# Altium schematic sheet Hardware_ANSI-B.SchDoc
size 431 x 279 mm; Date: Not shown in title block; ApprovedBy: Not shown in title block; CheckedBy: Not shown in title block; Author: Not shown in title block; CompanyName: Not shown in title block; Engineer: Not shown in title block; Organization: Not shown in title block; Address1: Not shown in title block; Address2: Not shown in title block; Address3: Not shown in title block; Address4: Not shown in title block; DocumentNumber: 1; Revision: Use project parameter SCH_Rev; SheetNumber: 1; SheetTotal: 1; PageSetup: Record=PageOptions|CenterHorizontal=True|CenterVertical=True|PrintScale=1.00|XCorrection=1.00|YCorrection=1.00|PrintKind=0|BorderSize=5000000|LeftOffset=0|BottomOffset=0|Orientation=2|PaperLength=1000|PaperWidth=1000|Scale=100|PaperSource=15|PrintQuality=600|MediaType=1|DitherType=10|PaperKind=Letter|PrintScaleMode=1
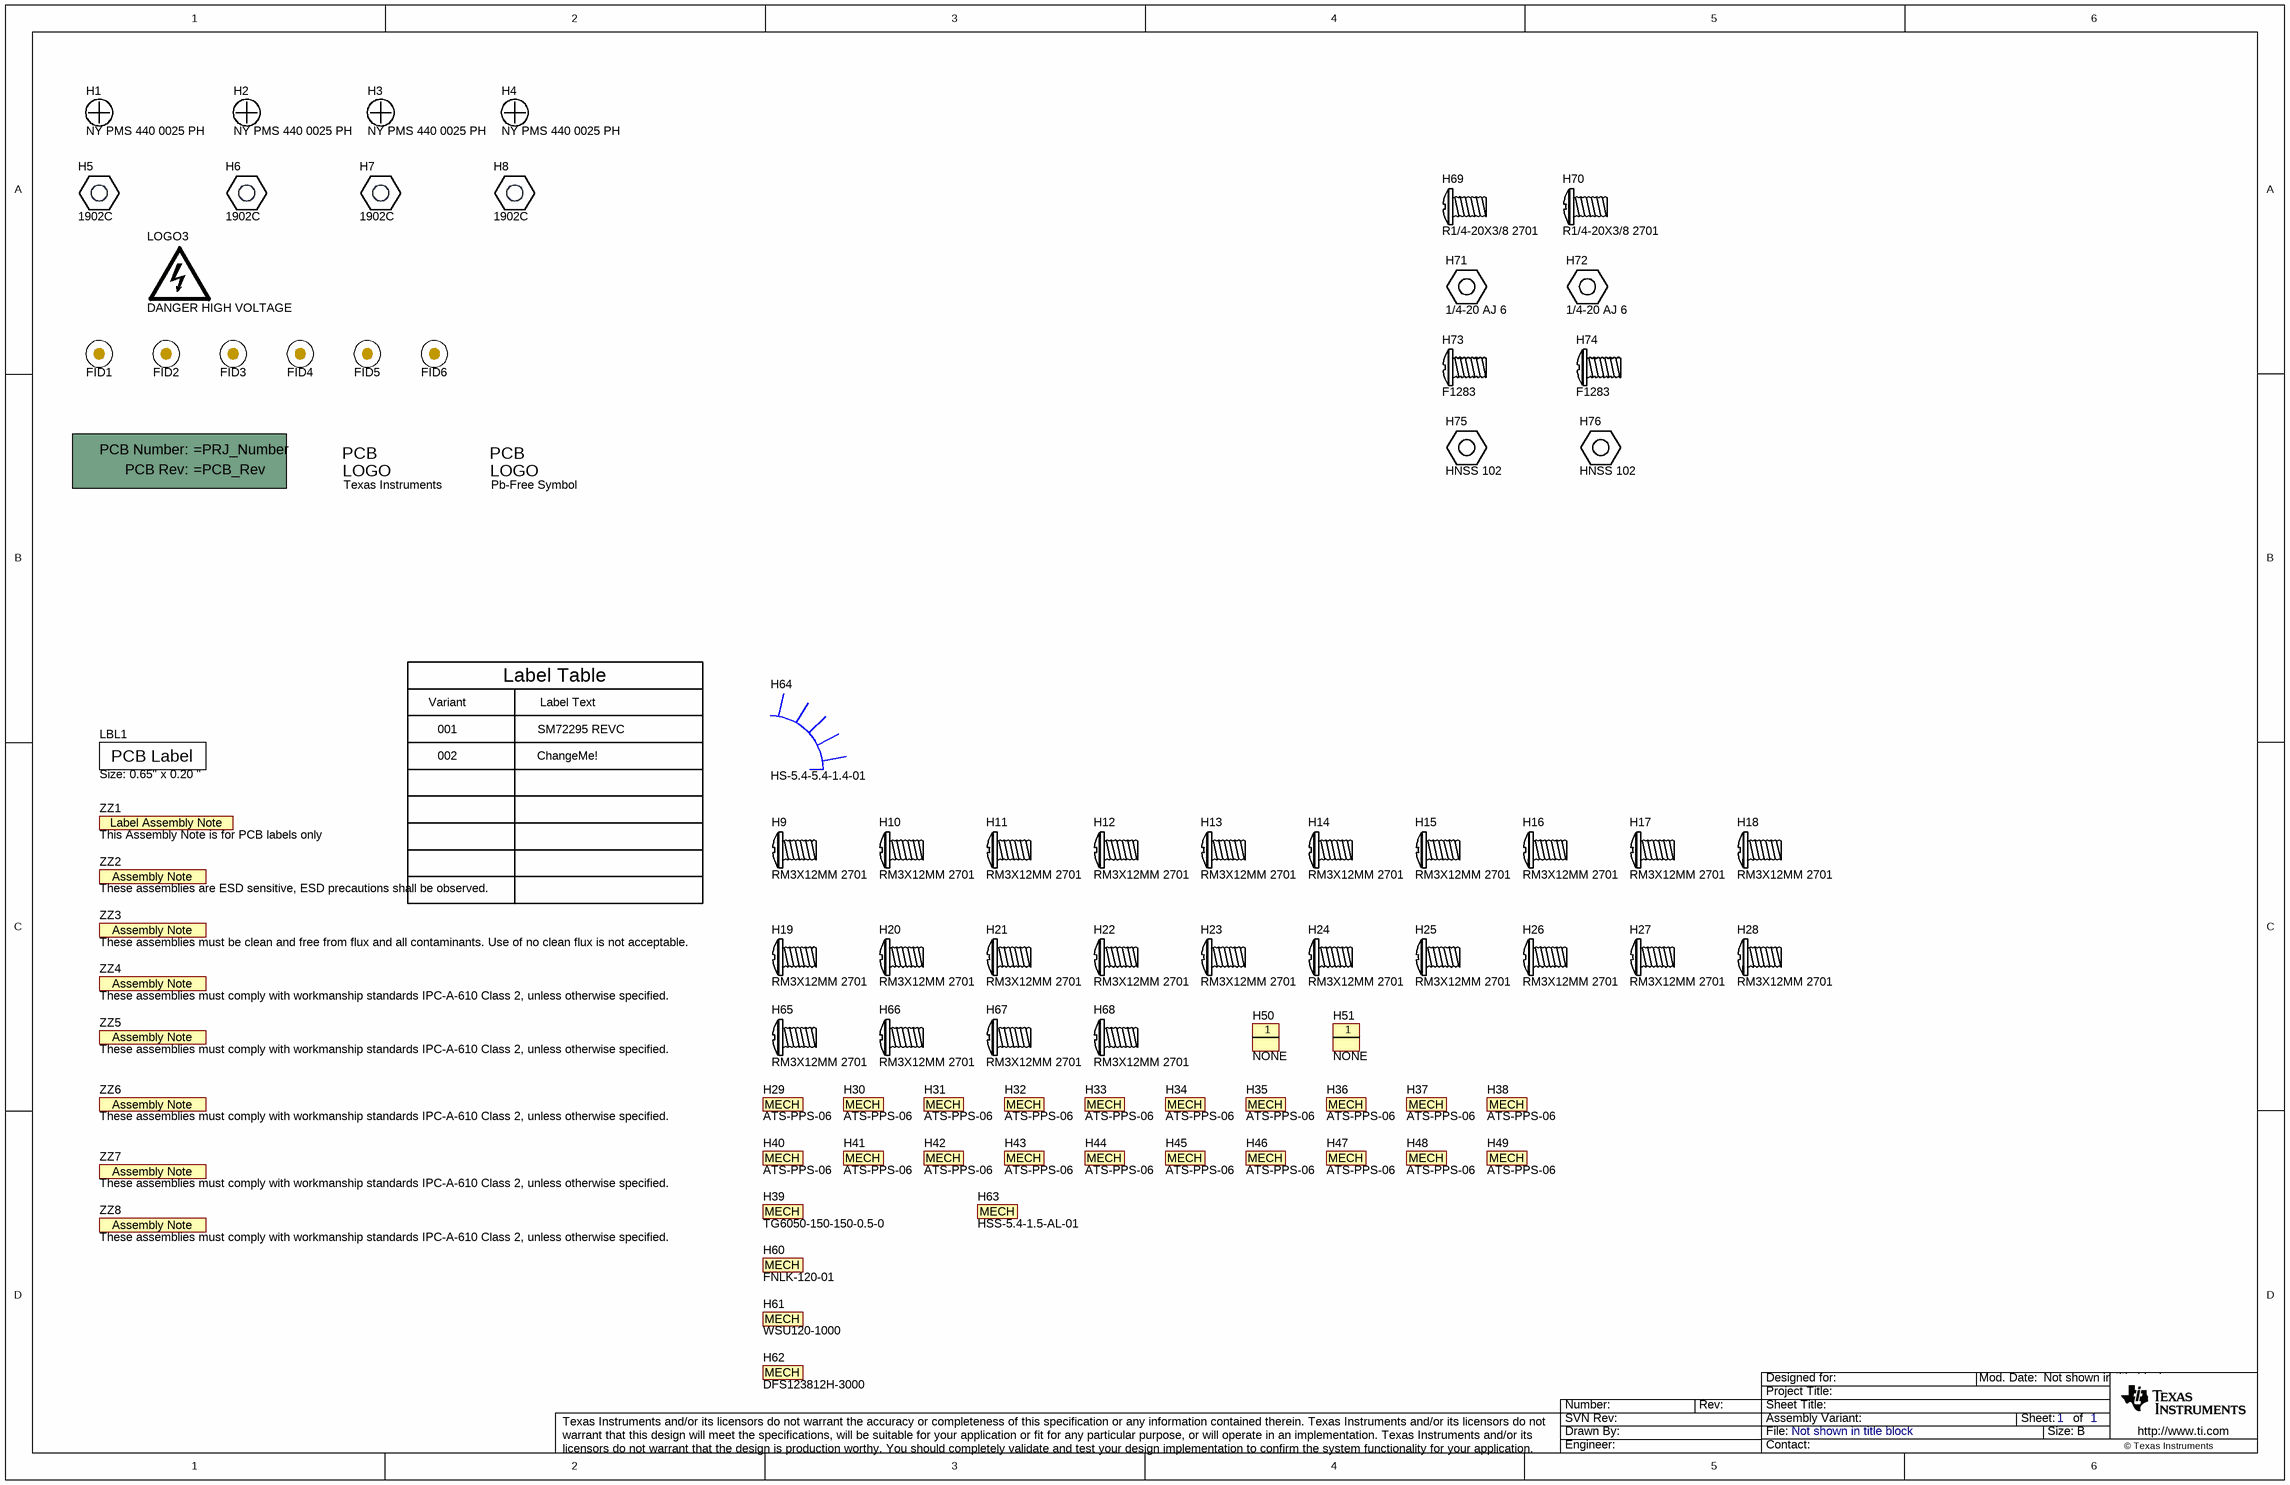
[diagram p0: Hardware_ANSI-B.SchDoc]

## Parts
!PCB1  Printed Circuit Board  (value not drawn)  (mechanical)
FID1  Fiducial  [Fiducial10-20]  (value not drawn)
FID2  Fiducial  [Fiducial10-20]  (value not drawn)
FID3  Fiducial  [Fiducial10-20]  (value not drawn)
FID4  Fiducial  [Fiducial10-20]  (value not drawn)
FID5  Fiducial  [Fiducial10-20]  (value not drawn)
FID6  Fiducial  [Fiducial10-20]  (value not drawn)
H1  NY PMS 440 0025 PH  [NY PMS 440 0025 PH]
H2  NY PMS 440 0025 PH  [NY PMS 440 0025 PH]
H3  NY PMS 440 0025 PH  [NY PMS 440 0025 PH]
H4  NY PMS 440 0025 PH  [NY PMS 440 0025 PH]
H5  1902C  [Keystone_1902C]
H6  1902C  [Keystone_1902C]
H7  1902C  [Keystone_1902C]
H8  1902C  [Keystone_1902C]
H9  RM3X12MM 2701  [APM_RM3X12MM_2701]
H10  RM3X12MM 2701  [APM_RM3X12MM_2701]
H11  RM3X12MM 2701  [APM_RM3X12MM_2701]
H12  RM3X12MM 2701  [APM_RM3X12MM_2701]
H13  RM3X12MM 2701  [APM_RM3X12MM_2701]
H14  RM3X12MM 2701  [APM_RM3X12MM_2701]
H15  RM3X12MM 2701  [APM_RM3X12MM_2701]
H16  RM3X12MM 2701  [APM_RM3X12MM_2701]
H17  RM3X12MM 2701  [APM_RM3X12MM_2701]
H18  RM3X12MM 2701  [APM_RM3X12MM_2701]
H19  RM3X12MM 2701  [APM_RM3X12MM_2701]
H20  RM3X12MM 2701  [APM_RM3X12MM_2701]
H21  RM3X12MM 2701  [APM_RM3X12MM_2701]
H22  RM3X12MM 2701  [APM_RM3X12MM_2701]
H23  RM3X12MM 2701  [APM_RM3X12MM_2701]
H24  RM3X12MM 2701  [APM_RM3X12MM_2701]
H25  RM3X12MM 2701  [APM_RM3X12MM_2701]
H26  RM3X12MM 2701  [APM_RM3X12MM_2701]
H27  RM3X12MM 2701  [APM_RM3X12MM_2701]
H28  RM3X12MM 2701  [APM_RM3X12MM_2701]
H29  ATS-PPS-06  (mechanical)
H30  ATS-PPS-06  (mechanical)
H31  ATS-PPS-06  (mechanical)
H32  ATS-PPS-06  (mechanical)
H33  ATS-PPS-06  (mechanical)
H34  ATS-PPS-06  (mechanical)
H35  ATS-PPS-06  (mechanical)
H36  ATS-PPS-06  (mechanical)
H37  ATS-PPS-06  (mechanical)
H38  ATS-PPS-06  (mechanical)
H39  TG6050-150-150-0.5-0  (mechanical)
H40  ATS-PPS-06  (mechanical)
H41  ATS-PPS-06  (mechanical)
H42  ATS-PPS-06  (mechanical)
H43  ATS-PPS-06  (mechanical)
H44  ATS-PPS-06  (mechanical)
H45  ATS-PPS-06  (mechanical)
H46  ATS-PPS-06  (mechanical)
H47  ATS-PPS-06  (mechanical)
H48  ATS-PPS-06  (mechanical)
H49  ATS-PPS-06  (mechanical)
H50  NONE  [HOLE INDUCTOR]
H51  NONE  [HOLE INDUCTOR]
H60  FNLK-120-01  (mechanical)
H61  WSU120-1000  (mechanical)
H62  DFS123812H-3000  (mechanical)
H63  HSS-5.4-1.5-AL-01  [Custom_HSS-5_4-1_5-AL-01]  (mechanical)
H64  HS-5.4-5.4-1.4-01  [Custom_HS-5_4-5_4-1_4-01]
H65  RM3X12MM 2701  [APM_RM3X12MM_2701]  (mechanical)
H66  RM3X12MM 2701  [APM_RM3X12MM_2701]  (mechanical)
H67  RM3X12MM 2701  [APM_RM3X12MM_2701]  (mechanical)
H68  RM3X12MM 2701  [APM_RM3X12MM_2701]  (mechanical)
H69  R1/4-20X3/8 2701  (mechanical)
H70  R1/4-20X3/8 2701  (mechanical)
H71  1/4-20 AJ 6  (mechanical)
H72  1/4-20 AJ 6  (mechanical)
H73  F1283  (mechanical)
H74  F1283  (mechanical)
H75  HNSS 102  (mechanical)
H76  HNSS 102  (mechanical)
LBL1  Size: 0.65" x 0.20 "  [Label_650x200]
Logo1  Texas Instruments  [TI_Symbol_Overlay_Medium]  (no BOM)
Logo2  Pb-Free Symbol  [Pb-Free_Overlay_Small]  (no BOM)
LOGO3  DANGER HIGH VOLTAGE  [IEC_HighVoltage_Small]  (no BOM)
ZZ1  This Assembly Note is for PCB labels only  [AssemblyNoteLabel]  (no BOM)
ZZ2  These assemblies are ESD sensitive, ESD precautions shall be observed.  [AssemblyNote]  (no BOM)
ZZ3  These assemblies must be clean and free from flux and all contaminants. Use of no clean flux is not acceptable.  [AssemblyNote]  (no BOM)
ZZ4  These assemblies must comply with workmanship standards IPC-A-610 Class 2, unless otherwise specified.  [AssemblyNote]  (no BOM)
ZZ5  These assemblies must comply with workmanship standards IPC-A-610 Class 2, unless otherwise specified.  [AssemblyNote]  (no BOM)
ZZ6  These assemblies must comply with workmanship standards IPC-A-610 Class 2, unless otherwise specified.  [AssemblyNote]  (no BOM)
ZZ7  These assemblies must comply with workmanship standards IPC-A-610 Class 2, unless otherwise specified.  [AssemblyNote]  (no BOM)
ZZ8  These assemblies must comply with workmanship standards IPC-A-610 Class 2, unless otherwise specified.  [AssemblyNote]  (no BOM)

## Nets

Not connected (* = marked no-connect by the designer): H50 1; H51 1

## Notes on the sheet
- Variant
- Label Table
- Label Text
- 001
- 002
- ChangeMe!
- SM72295 REVC

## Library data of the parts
!PCB1 = PCB: Manufacturer: Any; SymbolCreator: a0412235
FID1-FID6 = Fiducial: Fiducial mark.  There is nothing to buy or mount.; SymbolCreator: codlsc
H1-H4 = NY PMS 440 0025 PH: Machine Screw, Round, #4-40 x 1/4, Nylon, Philips panhead; Manufacturer: B&F Fastener Supply; CompType: Hardware; SymbolCreator: codlsc; U/M: EA
H5-H8 = 1902C: Standoff, Hex, 0.5"L #4-40 Nylon; Manufacturer: Keystone; CompType: Hardware; SymbolCreator: a0412235
H9-H28 H65-H68 = RM3X12MM 2701: Machine Screw Pan PHILLIPS M3, TH; Manufacturer: APM HEXSEAL; SymbolCreator: a0412235; CompType: Standoff
H29-H38 H40-H49 = ATS-PPS-06: PushPIN™ Heat Sink Attachments, 14 mm; Manufacturer: Advanced Thermal Solutions; SymbolCreator: codlsc; CompType: Spring
H39 = TG6050-150-150-0.5-0: Ultra Soft Thermal Conductive Pad; Manufacturer: t-Global Technology; SymbolCreator: codlsc; CompType: Hardware
H50 H51 = HOLE INDUCTOR: Manufacturer: Used in BOM report; SymbolVersion: 2014 - 10 - 22; SymbolCreator: A0412036; CompType: Used in some BOM reports.  Useful for finding later.; U/M: EA
H60 = FNLK-120-01: Fan Leg Kit for 92mm and 120mm Fans, 1.25" elevation; Manufacturer: Custom; SymbolCreator: codlsc; CompType: Hardware
H61 = WSU120-1000: AC/DC Adapter, 12 V, 12 W; Manufacturer: Triad Magnetics; SymbolCreator: codlsc; CompType: AC/DA Adapter
H62 = DFS123812H-3000: Fan, DC 12 V, 120mm square x 38mm 134 CFM; Manufacturer: Scythe; SymbolCreator: codlsc
H63 = HSS-5.4-1.5-AL-01: Heat Sink Fan Shroud, 5.4x5.4x1.5 Inch; Manufacturer: Custom; SymbolCreator: codlsc; CompType: Fan Leg Kit
H64 = HS-5.4-5.4-1.4-01: Heat Sink 5.4 x 5.4 x 1.4 Inch; Manufacturer: Custom; SymbolCreator: a0412235
H69 H70 = R1/4-20X3/8 2701: MACH SCREW PAN PHILLIPS 1/4-20; Manufacturer: APM HEXSEAL; SymbolCreator: a0412235; CompType: Hardware
H71 H72 = 1/4-20 AJ 6: HEX SEAL NUT 7/16" STEEL 1/4-20; Manufacturer: APM HEXSEAL; SymbolCreator: a0412235; CompType: Hardware
H73 H74 = F1283: Screw Combination Head 10-32; Manufacturer: Keystone; SymbolCreator: a0412235; CompType: Hardware
H75 H76 = HNSS 102: Machine Screw Nut, Hex, 3/8??', Stn, Steel, 10-32; Manufacturer: B&F Fastener Supply; SymbolCreator: a0412235; CompType: Hardware
LBL1 = THT-14-423-10: Thermal Transfer Printable Labels, 0.650" W x 0.200" H - 10,000 per roll; Manufacturer: Brady; SymbolCreator: a0412235; CompType: Label
Logo1 = TI_Logo: Texas Instrument Corporate Signature; SymbolCreator: a0412235
Logo2 = Pb-Free: SymbolCreator: a0412235
LOGO3 = IEC_HighVoltage: IEC 61010-1 High Voltage Warning; SymbolCreator: a0412235
ZZ1 = AssemblyNoteLabel: SymbolCreator: a0412235
ZZ2-ZZ8 = AssemblyNote: SymbolCreator: codlsc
